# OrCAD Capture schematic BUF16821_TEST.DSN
size A
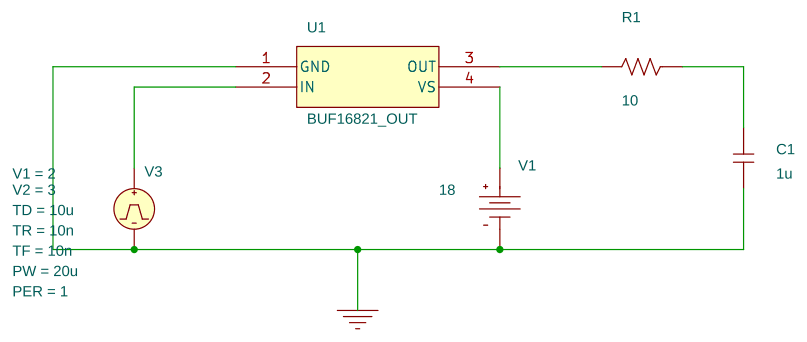
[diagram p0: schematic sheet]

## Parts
C1  1u  [RAD/CK05]
R1  10  [AX/RC05]
U1  BUF16821_OUT
V1  VDC
V3  VPULSE

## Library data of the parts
C1 = C
R1 = R
U1 = BUF16821_OUT
V1 = VDC: DC: 18
V3 = VPULSE: AC: 0; AppProp: Pulse$Voltage$1$-1; DC: 0; PER: 1; PW: 20u; TD: 10u; TF: 10n; TR: 10n; V1: 2; V2: 3

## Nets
0: C1.1 U1.1(GND) V1.1(-) V3.2(-)
N01213: R1.2 U1.3(OUT)
N01219: C1.2 R1.1
N01227: U1.2(IN) V3.1(+)
N01237: U1.4(VS) V1.0(+)
